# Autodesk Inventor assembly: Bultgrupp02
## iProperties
Created: 2001-12
Part Number: Bultgrupp02
Document SubType Name: Assembly
Designer: Tobben
Control State: 0
Master: False
Checked Out: False
Shininess: 64.0
Length Units: 11269
Angle Units: 11279
Time Units: 11290
Mass Units: 11283
Length Display Precision: 3
Angle Display Precision: 2
Density: 0.0
Volumn: 0.0
Area: 0.0
PropertySet Name: Model Information
Author: Tobben
